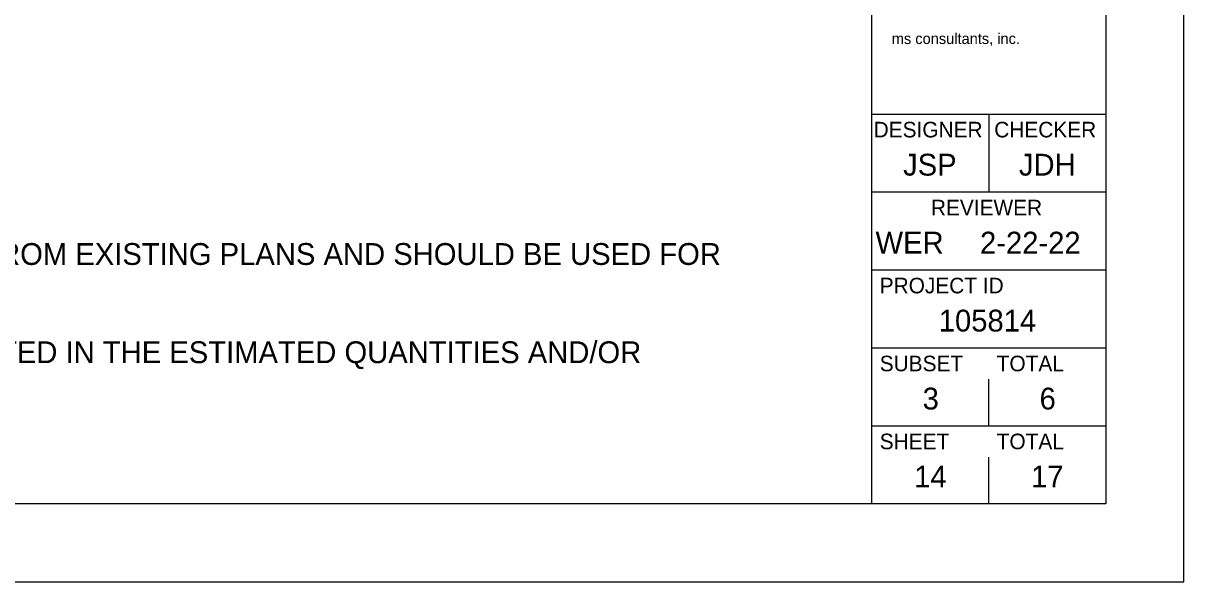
# Model space of a CAD drawing. Extents: x 0 to 34, y 0 to 22.
# Drawn here: x 26.56 to 34, y 0 to 3.58 of the extents above; entities that cross this region are included whole.
import ezdxf

# ---------------------------------------------------------------- set-up
doc = ezdxf.new("R2010")
doc.units = 0
for name, color, linetype in [('DR_P_Text', 7, 'Continuous'), ('SH_Border', 7, 'Continuous'), ('SH_Cut_Line', 7, 'Continuous'), ('SH_Data', 7, 'Continuous')]:
    doc.layers.add(name, color=color, linetype=linetype)

msp = doc.modelspace()

# ---------------------------------------------------------------- linework, layer by layer
at = {"layer": 'SH_Border'}
for p, q in [((32, 0.5), (32, 21.5)), ((32, 3), (33.5, 3)), ((32.75, 3), (32.75, 2.5)), ((32, 2.5), (33.5, 2.5)), ((32, 2), (33.5, 2)), ((32, 1.5), (33.5, 1.5)), ((32, 1), (33.5, 1))]:
    msp.add_line(p, q, dxfattribs=at)
msp.add_lwpolyline([(1.5, 21.5), (33.5, 21.5), (33.5, 0.5), (1.5, 0.5)], close=True, dxfattribs=at)
at = {"layer": 'SH_Cut_Line'}
msp.add_lwpolyline([(0, 0), (34, 0), (34, 22), (0, 22)], close=True, dxfattribs=at)
at = {"layer": 'SH_Data'}
for p, q in [((32.75, 1), (32.75, 1.3)), ((32.75, 0.5), (32.75, 0.8)), ((32.375, 0.675), (32.375, 0.675))]:
    msp.add_line(p, q, dxfattribs=at)

# ---------------------------------------------------------------- texts
at = {"layer": 'DR_P_Text'}
for s, p in [('DETAILS ON THIS SHEET ARE TAKEN FROM EXISTING PLANS AND SHOULD BE USED FOR', (22.8548, 2.0322)), ('PERFORM ONLY THE WORK AS INDICATED IN THE ESTIMATED QUANTITIES AND/OR ', (22.8548, 1.4022))]:
    msp.add_text(s, height=0.14, dxfattribs=at).set_placement(p)
at = {"layer": 'SH_Border'}
msp.add_text('ms consultants, inc.', height=0.07, rotation=360, dxfattribs=at).set_placement((32.1273, 3.4489))
at = {"layer": 'SH_Data'}
for s, height, p in [('DESIGNER', 0.1, (32.011, 2.85)), ('CHECKER', 0.1, (32.7843, 2.85)), ('JSP', 0.14, (32.1998, 2.605)), ('JDH', 0.14, (32.9427, 2.605)), ('REVIEWER', 0.1, (32.3783, 2.35)), ('WER', 0.14, (32.0231, 2.105)), ('2-22-22', 0.14, (32.6932, 2.105)), ('PROJECT ID', 0.1, (32.05, 1.85)), ('105814', 0.14, (32.4285, 1.605)), ('SUBSET', 0.1, (32.05, 1.35)), ('TOTAL', 0.1, (32.8, 1.35)), ('3', 0.14, (32.3251, 1.105)), ('6', 0.14, (33.0751, 1.105)), ('SHEET', 0.1, (32.05, 0.85)), ('TOTAL', 0.1, (32.8, 0.85)), ('14', 0.14, (32.271, 0.605)), ('17', 0.14, (33.0207, 0.605))]:
    msp.add_text(s, height=height, dxfattribs=at).set_placement(p)

doc.saveas('drawing.dxf')
